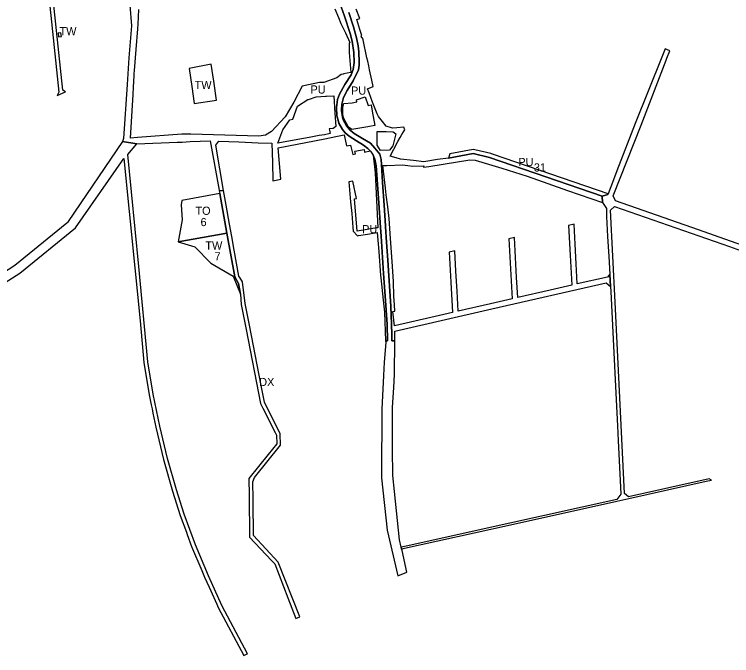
# Model space of a CAD drawing. Extents: x -521882 to -518995, y -1142400 to -1140153.
# Drawn here: x -520739 to -519863, y -1141816 to -1141032 of the extents above; entities that cross this region are included whole.
import ezdxf

# ---------------------------------------------------------------- set-up
doc = ezdxf.new("R2010")
doc.units = 0
for name, color, linetype in [('90320013', 7, 'Continuous'), ('90370013', 7, 'Continuous'), ('90390013', 7, 'Continuous'), ('90390023', 7, 'Continuous'), ('90430023', 7, 'Continuous'), ('90450013', 7, 'Continuous'), ('90450023', 7, 'Continuous'), ('ID_navrh', 7, 'Continuous')]:
    doc.layers.add(name, color=color, linetype=linetype)

msp = doc.modelspace()

# ---------------------------------------------------------------- linework, layer by layer
at = {"layer": '90320013'}
msp.add_lwpolyline([(-520342.18, -1141017.11), (-520335.75, -1141034.28), (-520328.86, -1141055.37), (-520326.63, -1141065), (-520324.51, -1141078.81), (-520324.16, -1141090.88), (-520325.35, -1141099.6), (-520327.56, -1141105.89), (-520335.59, -1141118), (-520342.14, -1141129.51), (-520344.38, -1141136.25), (-520345.84, -1141145.82), (-520345.14, -1141156.25), (-520343.69, -1141161.58), (-520342.68, -1141165.24), (-520338.22, -1141172.95), (-520335.19, -1141176.69), (-520330.27, -1141180.78), (-520321.21, -1141186.85), (-520312.59, -1141191.95), (-520307.43, -1141195.9), (-520304.49, -1141199.02), (-520304.21, -1141199.32), (-520301.55, -1141202.8), (-520300.95, -1141204.15), (-520298.67, -1141209.18), (-520297.11, -1141217.05), (-520293.97, -1141262.32), (-520291.98, -1141292.42), (-520291.26, -1141303.35), (-520288.07, -1141348.91), (-520285.88, -1141381.79), (-520283.95, -1141411.07), (-520283.46, -1141431.12), (-520285.62, -1141431.18), (-520285.53, -1141433.12), (-520287.25, -1141456.97), (-520288.42, -1141473.23), (-520290.19, -1141514.57), (-520290.52, -1141595.71), (-520290.53, -1141598.43), (-520283.67, -1141662.22), (-520270.75, -1141718.04), (-520259.91, -1141713.53), (-520265.6, -1141687.35), (-520266.08, -1141685.14), (-520266.52, -1141683.24), (-520268.73, -1141674.23), (-520274.84, -1141614.95), (-520276.82, -1141595.78), (-520276.93, -1141594.74), (-520277.03, -1141563.71), (-520277.2, -1141512.43), (-520275.67, -1141487.93), (-520274.69, -1141472.35), (-520274.48, -1141431.01), (-520277.92, -1141430.99), (-520277.86, -1141423.4), (-520278.27, -1141410.62), (-520279.11, -1141388.58), (-520280.36, -1141370.5), (-520281.66, -1141351.81), (-520282.86, -1141332.45), (-520284.36, -1141310.52), (-520285.69, -1141291.6), (-520285.78, -1141290.4), (-520287.43, -1141265.4), (-520289.28, -1141237.74), (-520290.72, -1141215.76), (-520290.93, -1141209.43), (-520292.63, -1141202.98), (-520298.66, -1141195.42), (-520304, -1141189.53), (-520313.7, -1141183.68), (-520323.9, -1141177.63), (-520328.85, -1141173.77), (-520333.5, -1141168.21), (-520337.34, -1141161.13), (-520338.41, -1141157.75), (-520339.64, -1141149.76), (-520339.09, -1141141.84), (-520337.15, -1141133.73), (-520332.74, -1141125.19), (-520325.12, -1141113.35), (-520318.78, -1141100.08), (-520318.04, -1141094.37), (-520317.76, -1141090.48), (-520318.44, -1141077.73), (-520319.27, -1141070.53), (-520321.07, -1141060.89), (-520324.76, -1141047.17), (-520330.66, -1141029.65)], dxfattribs=at)
at = {"layer": '90370013'}
for points in [[(-520700.46, -1140980.02), (-520694.75, -1141033.39), (-520684.73, -1141127.15), (-520686.99, -1141131.09), (-520676.95, -1141126.77), (-520679.92, -1141124.76), (-520699.09, -1140943.92)], [(-519789.84, -1141335.36), (-519864.09, -1141309.46), (-519903.26, -1141295.46), (-520004.78, -1141260.17), (-520007.53, -1141254.06), (-519973.57, -1141167.53), (-519942.77, -1141088.03), (-519941.9, -1141085.78), (-519938.17, -1141076.59), (-519944.08, -1141074.41), (-519948.1, -1141084.44), (-519980.55, -1141165.39), (-520002.99, -1141223.35), (-520007.17, -1141234.15), (-520013.82, -1141251.35), (-520014.17, -1141252.24), (-520020.92, -1141254.2), (-520020.82, -1141261.97), (-520015.63, -1141269.2), (-520015.8, -1141279.3), (-520014.41, -1141303.65), (-520013.01, -1141327.96), (-520011.78, -1141349.43), (-520010.91, -1141364.55), (-520010.61, -1141370.65), (-520007.71, -1141429.14), (-520004.05, -1141503.1), (-520002.49, -1141534.74), (-520001.59, -1141552.99), (-519998.35, -1141618.37), (-520003.08, -1141624.98), (-520133.69, -1141653.91), (-520260.66, -1141681.95)], [(-520768.7, -1141371.01), (-520732.72, -1141348.25), (-520664.52, -1141292.81), (-520605.35, -1141208.42), (-520585.72, -1141406.64), (-520580.93, -1141457.51), (-520574.39, -1141497.17), (-520572, -1141509.22), (-520571.03, -1141514.08), (-520569.98, -1141519.36), (-520566.58, -1141536.47), (-520557.06, -1141576.08), (-520545.85, -1141614.67), (-520536.49, -1141644.52), (-520529.1, -1141664.77), (-520528.04, -1141667.68), (-520522.71, -1141682.28), (-520510.4, -1141711.55), (-520506.95, -1141719.75), (-520501.37, -1141732.13), (-520491.98, -1141752.99), (-520490.19, -1141756.96), (-520458.87, -1141815.72), (-520454.91, -1141813.57), (-520454.47, -1141813.35), (-520485.78, -1141754.61), (-520502.23, -1141718.09), (-520518.1, -1141680.34), (-520531.72, -1141643.02), (-520541.05, -1141613.27), (-520552.2, -1141574.91), (-520561.68, -1141535.49), (-520569.46, -1141496.36), (-520576, -1141456.7), (-520587.35, -1141340.09), (-520600.66, -1141203.4), (-520589.77, -1141190.43), (-520607.02, -1141187.64), (-520665.65, -1141273.94), (-520674.18, -1141286.49), (-520675.31, -1141287.41)], [(-520390.37, -1141768.15), (-520417.08, -1141701.53), (-520447.22, -1141669.1), (-520447.6, -1141627.85), (-520447.63, -1141624.46), (-520447.82, -1141603.5), (-520446.02, -1141598.19), (-520414.26, -1141558.37), (-520414.56, -1141544.64), (-520433.82, -1141506.13), (-520437.82, -1141485.59), (-520452.14, -1141412.08), (-520457.31, -1141385.57), (-520460.62, -1141358.83), (-520463.71, -1141353.8), (-520464.8, -1141352.03), (-520470.52, -1141320.08), (-520473.45, -1141303.71), (-520476.2, -1141288.34), (-520480.37, -1141265.08), (-520483.58, -1141247.19), (-520488.89, -1141247.94), (-520488.31, -1141251.1), (-520479.49, -1141299.41), (-520469.72, -1141352.88), (-520465.21, -1141361), (-520463.1, -1141373.93), (-520462.06, -1141386.7), (-520456.11, -1141417.28), (-520438.53, -1141507.64), (-520436.83, -1141511), (-520435.68, -1141513.27), (-520420.69, -1141542.88), (-520419, -1141546.21), (-520418.4, -1141556.83), (-520428.95, -1141569.87), (-520452.66, -1141599.19), (-520452.43, -1141620.06), (-520451.86, -1141671.07), (-520425.12, -1141699.44), (-520421.11, -1141703.69), (-520405.02, -1141744.98), (-520395.26, -1141770.17), (-520390.37, -1141768.15)], [(-520260.66, -1141681.95), (-520266.52, -1141683.24), (-520266.08, -1141685.14), (-520133.25, -1141655.87), (-520003.05, -1141627.05), (-519988.36, -1141623.57), (-519894.12, -1141602.61), (-519887.54, -1141601.15), (-519890.16, -1141599.67), (-519988.83, -1141621.62), (-519993.67, -1141617.6), (-520005.29, -1141383.92), (-520010.89, -1141271.2), (-520005.98, -1141266.96), (-519865.42, -1141315.8), (-519825.24, -1141330.38)], [(-520675.31, -1141287.41), (-520738.6, -1141338.95), (-520773.04, -1141360.9)]]:
    msp.add_lwpolyline(points, dxfattribs=at)
at = {"layer": '90390013'}
for points in [[(-520681.75, -1141059.18), (-520682.32, -1141054.61), (-520685.9, -1141055.06), (-520685.33, -1141059.63), (-520681.75, -1141059.18)], [(-520498.69, -1141092.95), (-520525.62, -1141098.2), (-520522.42, -1141120.25), (-520519.42, -1141140.9), (-520492.31, -1141136.96), (-520495.67, -1141113.78), (-520498.69, -1141092.95)]]:
    msp.add_lwpolyline(points, dxfattribs=at)
at = {"layer": '90390023'}
msp.add_lwpolyline([(-520479.49, -1141299.41), (-520539.2, -1141310.09), (-520518.61, -1141316.36), (-520499.06, -1141336.21), (-520471.76, -1141351.9), (-520463.1, -1141373.93), (-520465.21, -1141361), (-520469.72, -1141352.88), (-520479.49, -1141299.41)], dxfattribs=at)
at = {"layer": '90430023'}
msp.add_lwpolyline([(-520488.31, -1141251.1), (-520534.84, -1141259.42), (-520535.3, -1141264.93), (-520534.35, -1141283.17), (-520539.2, -1141310.09), (-520479.49, -1141299.41), (-520488.31, -1141251.1)], dxfattribs=at)
at = {"layer": '90450013'}
for points in [[(-520601.54, -1141117.64), (-520606.07, -1141183.78), (-520607.02, -1141187.64), (-520589.77, -1141190.43), (-520540.34, -1141188.43), (-520534.17, -1141188.18), (-520524.27, -1141187.6), (-520500.08, -1141186.63), (-520490.28, -1141240.29), (-520489.54, -1141244.37), (-520488.89, -1141247.94), (-520483.58, -1141247.19), (-520488.14, -1141220.84), (-520493.12, -1141191.96), (-520489.31, -1141186.91), (-520464.88, -1141187.85), (-520441.37, -1141189.15), (-520424.53, -1141189.37), (-520423.9, -1141213.13), (-520423.33, -1141235.38), (-520413.51, -1141233.43), (-520416.76, -1141195.21), (-520359.99, -1141184.11), (-520346.46, -1141181.44), (-520336.24, -1141179.42), (-520333.6, -1141192.88), (-520328.4, -1141191.92), (-520325.76, -1141203.31), (-520322.39, -1141202.63), (-520323.1, -1141199.37), (-520312, -1141197.1), (-520311.28, -1141200.4), (-520304.49, -1141199.02), (-520307.43, -1141195.9), (-520312.59, -1141191.95), (-520321.21, -1141186.85), (-520330.27, -1141180.78), (-520335.19, -1141176.69), (-520338.22, -1141172.95), (-520342.68, -1141165.24), (-520343.69, -1141161.58), (-520345.14, -1141156.25), (-520345.84, -1141145.82), (-520344.38, -1141136.25), (-520342.14, -1141129.51), (-520335.59, -1141118), (-520327.56, -1141105.89), (-520325.35, -1141099.6), (-520324.16, -1141090.88), (-520324.51, -1141078.81), (-520326.63, -1141065), (-520328.86, -1141055.37), (-520335.75, -1141034.28), (-520342.18, -1141017.11)], [(-520598.37, -1141020.83), (-520596.21, -1141046.3), (-520599.33, -1141085.41), (-520601.54, -1141117.64)], [(-520347.88, -1141025.34), (-520343.25, -1141036.1), (-520340.18, -1141043.47), (-520334.74, -1141054.84), (-520329.51, -1141066.36), (-520330.22, -1141066.74), (-520330.35, -1141078.64), (-520328.09, -1141103.27), (-520337.09, -1141104.85), (-520337.04, -1141105.09), (-520339.78, -1141105.62), (-520345.24, -1141109.63), (-520361.02, -1141115.3), (-520366.58, -1141115.24), (-520387.46, -1141120.02), (-520397.97, -1141139.24), (-520408.18, -1141157.48), (-520425.27, -1141175.41), (-520432.59, -1141179.7), (-520440.68, -1141181.04), (-520523.78, -1141178.47), (-520526.48, -1141178.44), (-520530.26, -1141178.39), (-520534.49, -1141178.34), (-520588.63, -1141182.42), (-520597.46, -1141183.55), (-520594.25, -1141129.86), (-520593.72, -1141120.93), (-520592.91, -1141107.42), (-520592.76, -1141104.85), (-520592.43, -1141100.83), (-520590.32, -1141074.97), (-520588.29, -1141049.68), (-520587.85, -1141044.25), (-520586.99, -1141025.98)], [(-520300.97, -1141120.47), (-520302.64, -1141112.56), (-520305.34, -1141099.75), (-520306.28, -1141094.87), (-520307.52, -1141089.35), (-520308.39, -1141085.31), (-520313.18, -1141063.23), (-520313.88, -1141060.82), (-520314.63, -1141061.07), (-520315.46, -1141058.39), (-520314.7, -1141058.15), (-520317.05, -1141050.62), (-520320.97, -1141038.48), (-520317.01, -1141037.16), (-520321.6, -1141025.87)], [(-520330.66, -1141029.65), (-520324.76, -1141047.17), (-520321.07, -1141060.89), (-520319.27, -1141070.53), (-520318.44, -1141077.73), (-520317.76, -1141090.48), (-520318.04, -1141094.37), (-520318.78, -1141100.08), (-520325.12, -1141113.35), (-520332.74, -1141125.19), (-520337.15, -1141133.73), (-520339.09, -1141141.84), (-520339.64, -1141149.76), (-520338.41, -1141157.75), (-520337.34, -1141161.13), (-520333.5, -1141168.21), (-520328.85, -1141173.77), (-520323.9, -1141177.63), (-520313.7, -1141183.68), (-520304, -1141189.53), (-520298.66, -1141195.42), (-520292.63, -1141202.98), (-520290.93, -1141209.43), (-520290.72, -1141215.76), (-520289.28, -1141237.74), (-520287.43, -1141265.4), (-520285.78, -1141290.4), (-520285.69, -1141291.6), (-520284.36, -1141310.52), (-520282.86, -1141332.45), (-520281.66, -1141351.81), (-520280.36, -1141370.5), (-520279.11, -1141388.58), (-520278.27, -1141410.62), (-520277.86, -1141423.4), (-520277.92, -1141430.99), (-520274.48, -1141431.01), (-520274.28, -1141419.2), (-520155.8, -1141392.1), (-520016.19, -1141360.33), (-520010.91, -1141364.55), (-520011.78, -1141349.43), (-520014.56, -1141353.06), (-520051.44, -1141361.51), (-520052.77, -1141337.11), (-520054.09, -1141312.76), (-520055.42, -1141288.36), (-520062.28, -1141289.92), (-520060.29, -1141326.5), (-520058.3, -1141363.08), (-520084.7, -1141369.12), (-520124.29, -1141378.19), (-520125.62, -1141353.79), (-520126.95, -1141329.38), (-520128.28, -1141304.98), (-520135.15, -1141306.52), (-520133.15, -1141343.14), (-520131.16, -1141379.76), (-520157.5, -1141385.79), (-520196.98, -1141394.82), (-520198.32, -1141370.3), (-520199.66, -1141345.79), (-520200.99, -1141321.26), (-520207.86, -1141322.8), (-520205.86, -1141359.46), (-520203.85, -1141396.38), (-520230.23, -1141402.41), (-520274.78, -1141412.59), (-520276.63, -1141395.38), (-520274.32, -1141394.81), (-520274.78, -1141387.08), (-520275.42, -1141376.5), (-520276.18, -1141358.36), (-520277.43, -1141340.16), (-520280.23, -1141299.79), (-520281.48, -1141281.72), (-520283.12, -1141267.46), (-520284.8, -1141252.79), (-520285.74, -1141244.64), (-520288.93, -1141216.9), (-520284.22, -1141216.65), (-520265.11, -1141215.87), (-520258.35, -1141216.74), (-520252.46, -1141217.61), (-520239.12, -1141217.25), (-520239.26, -1141218.7), (-520232.83, -1141217.82), (-520215.27, -1141215.02), (-520182.91, -1141209.86), (-520176.27, -1141210.31), (-520143.54, -1141220.12), (-520112.81, -1141229.84), (-520087.52, -1141238.96), (-520063.43, -1141247.22), (-520020.82, -1141261.97), (-520020.92, -1141254.2), (-520158.56, -1141206.98), (-520178.85, -1141202.22), (-520209, -1141207.86), (-520222.29, -1141209.66), (-520239.07, -1141212.2), (-520251.72, -1141210.86), (-520267.32, -1141208.86), (-520272.66, -1141207.5), (-520280.13, -1141205.59), (-520275.56, -1141196.82), (-520270.74, -1141187.55), (-520267.83, -1141182.58), (-520265.8, -1141179.08), (-520263.7, -1141175.46), (-520262.34, -1141173.28), (-520263.33, -1141170.08), (-520271.87, -1141170.72), (-520277.22, -1141171.12), (-520285.07, -1141168.6), (-520289.43, -1141163.17), (-520294.54, -1141156.83), (-520296.03, -1141153.59), (-520301.56, -1141139.26), (-520305.82, -1141127.93), (-520307.67, -1141123.05), (-520300.97, -1141120.47)], [(-520392.71, -1141184.99), (-520417.36, -1141189.63), (-520411.3, -1141173.03), (-520402.63, -1141160.92), (-520399.1, -1141160.34), (-520393.37, -1141144.49), (-520380.82, -1141136.27), (-520379.87, -1141135.97), (-520370.32, -1141133), (-520359.15, -1141132.28), (-520357.95, -1141132.21), (-520349.11, -1141131.64), (-520347.61, -1141152.91), (-520347.81, -1141152.92), (-520346.65, -1141169.3), (-520349.86, -1141171.48), (-520354.71, -1141171.83), (-520354.34, -1141173.71), (-520353.47, -1141177.71), (-520360.34, -1141179.18), (-520366.93, -1141180.34), (-520378.86, -1141182.41), (-520392.71, -1141184.99)]]:
    msp.add_lwpolyline(points, dxfattribs=at)
for points in [[(-520337.89, -1141145.94), (-520336.61, -1141141.05), (-520326.63, -1141140.31), (-520320.69, -1141138.98), (-520321.22, -1141136.45), (-520310.58, -1141132.78), (-520307.07, -1141143.41), (-520303.47, -1141142.76), (-520302.11, -1141150.23), (-520298.87, -1141168.07), (-520307.53, -1141169.64), (-520319.49, -1141171.67), (-520326.87, -1141172.95), (-520330.81, -1141170.06), (-520336.67, -1141159.38), (-520338.08, -1141155.23), (-520338.1, -1141152.71)], [(-520292.9, -1141175.16), (-520287.4, -1141175.25), (-520284.8, -1141175.38), (-520276.61, -1141175.8), (-520273.02, -1141178.12), (-520276.81, -1141192.82), (-520280.99, -1141198.2), (-520291.83, -1141198.59), (-520295.98, -1141192.02), (-520296.01, -1141175.11)], [(-520325.59, -1141235.8), (-520330.62, -1141236.74), (-520328.39, -1141261.02), (-520327.05, -1141275.53), (-520325.5, -1141292.44), (-520325.09, -1141296.95), (-520320.11, -1141302.71), (-520318.74, -1141302.49), (-520307.88, -1141300.74), (-520298.25, -1141299.19), (-520296, -1141298.82), (-520294.09, -1141322.02), (-520291.7, -1141351.03), (-520291.41, -1141353.94), (-520288.69, -1141381.19), (-520287.2, -1141396.11), (-520285.62, -1141431.18), (-520283.46, -1141431.12), (-520283.95, -1141411.07), (-520285.88, -1141381.79), (-520288.07, -1141348.91), (-520291.26, -1141303.35), (-520291.98, -1141292.42), (-520293.97, -1141262.32), (-520297.11, -1141217.05), (-520298.67, -1141209.18), (-520300.95, -1141204.15), (-520298.61, -1141225.85), (-520295.11, -1141292.82), (-520296.48, -1141293.05), (-520320.29, -1141297.03), (-520323.62, -1141257.49), (-520321.16, -1141257.11)]]:
    msp.add_lwpolyline(points, close=True, dxfattribs=at)
at = {"layer": '90450023'}
msp.add_lwpolyline([(-520013.82, -1141251.35), (-520153.86, -1141203.31), (-520156.44, -1141202.42), (-520157.17, -1141202.17), (-520176.64, -1141197.6), (-520178.73, -1141197.11), (-520207.36, -1141202.47), (-520209, -1141207.86), (-520178.85, -1141202.22), (-520158.56, -1141206.98), (-520020.92, -1141254.2), (-520014.17, -1141252.24), (-520013.82, -1141251.35)], dxfattribs=at)

# ---------------------------------------------------------------- texts
at = {"layer": '90370013'}
msp.add_text('DX', height=10, rotation=360, dxfattribs=at).set_placement((-520440.13, -1141486.3))
at = {"layer": '90390013'}
for rotation, p in [(360, (-520684.17, -1141057.71)), (0, (-520519.04, -1141123.41))]:
    msp.add_text('TW', height=10, rotation=rotation, dxfattribs=at).set_placement(p)
at = {"layer": '90390023'}
msp.add_text('TW', height=10, rotation=0, dxfattribs=at).set_placement((-520505.93, -1141319.64))
at = {"layer": '90430023'}
msp.add_text('TO', height=10, rotation=0, dxfattribs=at).set_placement((-520518.06, -1141277.07))
at = {"layer": '90450013'}
for rotation, p in [(0, (-520377.46, -1141128.93)), (0, (-520327.95, -1141130.26)), (360, (-520314.34, -1141299.63))]:
    msp.add_text('PU', height=10, rotation=rotation, dxfattribs=at).set_placement(p)
at = {"layer": '90450023'}
msp.add_text('PU', height=10, rotation=0, dxfattribs=at).set_placement((-520123.53, -1141217.56))
at = {"layer": 'ID_navrh'}
for s, rotation, p in [('31', 360, (-520104.55, -1141224.17)), ('6', 360, (-520511.77, -1141290.87)), ('7', 0, (-520494.7, -1141332.77))]:
    msp.add_text(s, height=10, rotation=rotation, dxfattribs=at).set_placement(p)

doc.saveas('drawing.dxf')
